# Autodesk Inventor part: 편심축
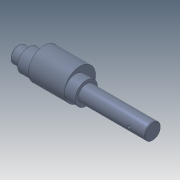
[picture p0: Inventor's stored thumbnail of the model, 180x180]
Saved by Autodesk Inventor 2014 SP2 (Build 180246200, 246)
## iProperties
Manager: 한국ATC센터
Company: 한국ATC센터
Created: 2014-07
Part Number: 편심축
Document SubType Name: Modeling
Designer: KYOUNG IL JANG
Density: 7.86 g/cm^3
Material: 강, 연강
Mass: 1544.74 g
Surface Area: 256.354 cm^2
Volume: 196.531 cm^3
Appearance: 강철
Author: KYOUNG IL JANG
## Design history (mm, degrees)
sketch "스케치1"
  geometry: L1 (-105, 0)-(105, 0); L2 (-105, 0)-(-105, 12.5); L3 (-105, 12.5)-(-89, 12.5); L4 (-89, 12.5)-(-89, 17.5); L5 (-89, 17.5)-(-82, 17.5); L6 (-82, 17.5)-(-82, 12.5); L7 (-82, 12.5)-(-0.35, 12.5); L8 (-0.35, 12.5)-(-0.35, 11.95); L9 (-0.35, 11.95)-(1, 11.95); L10 (1, 11.95)-(1, 12.5); L11 (1, 12.5)-(105, 12.5); L12 (105, 12.5)-(105, 0); L13 (70, 12.5)-(70, 9.1); L14 (70, 9.1)-(95, 9.1); L15 (95, 9.1)-(95, 12.5); L16 (80, -12.5)-(82.5, -12.5); L17 (82.5, -12.5)-(80, -10); L18 (80, -10)-(80, -12.5); L19 (1, 12.5)-(-0.35, 12.5); 2 further points
  constraints: 38 end point, 8 parallel, 5 collinear, 5 perpendicular, 2 point on line, 1 coincident, 1 horizontal, 1 midpoint, 1 vertical
  dimensions: "d0" = 210 distance of L1.start L1.end; "d1" = 25 diameter of L3 L1; "d2" = 35 diameter of L5 L1; "d3" = 16 distance of L2.end L3.end; "d6" = 1.35 distance of L8.end L9.end; "d7" = 23.9 diameter of L9 L1; "d8" = 3.4 distance between parallel lines of L14 L11; "d9" = 10 distance between parallel lines of L15 L12; "d10" = 25 distance of L13.end L14.end; "d11" = 25 diameter of L16 L1 (= d1); "d12" = 25 distance from line of L12 L16.start; "d13" = 45 deg angle of L17 L18; "d14" = 5 diameter of L16.end L18; "d27" = 104 distance between parallel lines of L10 L12; "d35" = 7 distance of L4.end L5.end
revolve "회전1" stored, may be unused: angle "d15" = 90 deg
revolve "회전2" stored, may be unused: angle "d16" = 90 deg
extrude "돌출1" cut sketch "스케치1" stored distance "d17" = 8; taper "d18" = 0 deg
fillet "모깎기1" dims "d19" = 4
node "작업 평면1"
sketch "스케치2"
  geometry: C1 r 12.5 at (0, 0) reference; C2 r 17.5 at (0, 0); C3 r 24.5 at (0, 7); 1 further point
  constraints: 2 centre point, 1 coincident, 1 tangent, 1 vertical alignment
  dimensions: "d32" = 35 diameter of C2; "d33" = 49 diameter of C3 (derived); "d34" = 7 distance of C3.centre point (0, 0)
extrude "돌출2" join sketch "스케치2" distance "d22" = 56; taper "d23" = 0 deg
chamfer "모따기1" distance "d24" = 1; stored, may be unused: second distance "d25" = 2, angle "d26" = 45 deg
feature "면 이동1" dims "d31" = 83
node "솔리드1"
